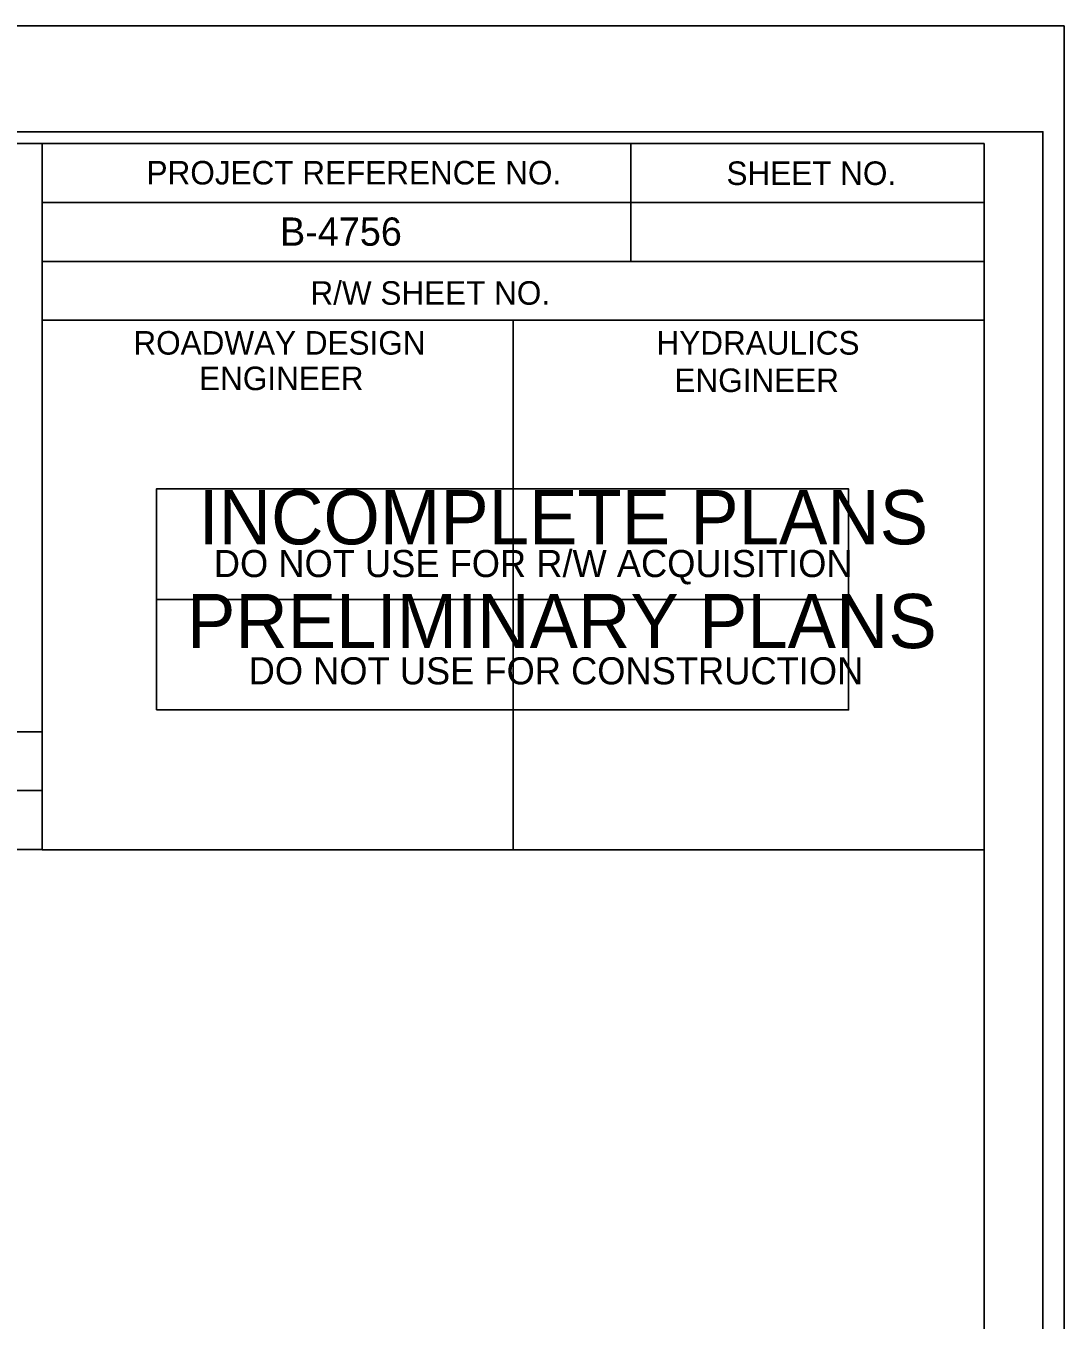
# Model space of a CAD drawing. Extents: x 2431000 to 2534000, y 645879 to 714000.
# Drawn here: x 2467565.7 to 2467786.2, y 672203.6 to 672478.6 of the extents above; entities that cross this region are included whole.
import ezdxf

# ---------------------------------------------------------------- set-up
doc = ezdxf.new("R2010")
doc.units = 0
for name, color, linetype in [('KHA_LOGO', 7, 'Continuous'), ('Prop Dimension', 7, 'Continuous'), ('Prop Dimension Text', 7, 'Continuous'), ('Prop Terminator CELL', 7, 'Continuous'), ('Sheet Clip Boundary CELL', 7, 'Continuous')]:
    doc.layers.add(name, color=color, linetype=linetype)

msp = doc.modelspace()

# ---------------------------------------------------------------- linework, layer by layer
at = {"layer": 'KHA_LOGO'}
for p, q in [((2467694.2, 672453.58), (2467694.2, 672428.58)), ((2467569.15, 672441.08), (2467769.2, 672441.08)), ((2467569.15, 672428.58), (2467769.2, 672428.58)), ((2467569.15, 672428.58), (2467569.15, 672416.08)), ((2467569.15, 672428.58), (2467769.2, 672428.58)), ((2467669.2, 672416.08), (2467669.2, 672303.63))]:
    msp.add_line(p, q, dxfattribs=at)
for points in [[(2467769.2, 672453.63), (2466269.2, 672453.63), (2466269.2, 671403.63), (2467769.2, 671403.63)], [(2467569.15, 672453.63), (2467769.2, 672453.63), (2467769.2, 672428.58), (2467569.15, 672428.58)], [(2467569.15, 672416.08), (2467669.2, 672416.08), (2467669.2, 672303.58), (2467569.15, 672303.58)], [(2467669.2, 672416.08), (2467769.2, 672416.08), (2467769.2, 672303.58), (2467669.2, 672303.58)]]:
    msp.add_lwpolyline(points, close=True, dxfattribs=at)
at = {"layer": 'Prop Dimension'}
msp.add_lwpolyline([(2466102.7, 671378.63), (2467786.2, 671378.63), (2467786.2, 672478.63), (2466102.7, 672478.63)], close=True, dxfattribs=at)
at = {"layer": 'Prop Dimension Text'}
for points in [[(2467593.43, 672356.76), (2467593.43, 672380.26), (2467740.43, 672380.26), (2467740.43, 672356.77)], [(2467593.43, 672333.27), (2467593.43, 672356.76), (2467740.43, 672356.77), (2467740.43, 672333.27)]]:
    msp.add_lwpolyline(points, close=True, dxfattribs=at)
at = {"layer": 'Prop Terminator CELL'}
msp.add_lwpolyline([(2466115.7, 671401.13), (2467781.7, 671401.13), (2467781.7, 672456.13), (2466115.7, 672456.13)], close=True, dxfattribs=at)
at = {"layer": 'Sheet Clip Boundary CELL'}
for points in [[(2467469.15, 672328.63), (2467569.15, 672328.63), (2467569.15, 672453.63), (2467469.15, 672453.63)], [(2467469.15, 672316.13), (2467569.15, 672316.13), (2467569.15, 672328.63), (2467469.15, 672328.63)], [(2467469.15, 672303.63), (2467569.15, 672303.63), (2467569.15, 672316.13), (2467469.15, 672316.13)]]:
    msp.add_lwpolyline(points, close=True, dxfattribs=at)

# ---------------------------------------------------------------- texts
at = {"layer": 'KHA_LOGO'}
for s, height, p in [('PROJECT REFERENCE NO.', 5.0001, (2467591.35, 672444.93)), ('SHEET NO.', 5, (2467714.5, 672444.83)), ('B-4756', 6, (2467619.69, 672431.92)), ('R/W SHEET NO.', 5.0001, (2467626.15, 672419.38)), ('ROADWAY DESIGN', 5.0001, (2467588.55, 672408.78)), ('HYDRAULICS', 5, (2467699.65, 672408.78)), ('ENGINEER', 5, (2467602.5, 672401.23)), ('ENGINEER', 5, (2467703.45, 672400.83))]:
    msp.add_text(s, height=height, dxfattribs=at).set_placement(p)
at = {"layer": 'Prop Dimension Text'}
for s, height, p in [('INCOMPLETE PLANS', 11.52, (2467602.38, 672368.47)), ('DO NOT USE FOR R/W ACQUISITION', 5.76, (2467605.63, 672361.51)), ('PRELIMINARY PLANS', 11.52, (2467599.93, 672346.41)), ('DO NOT USE FOR CONSTRUCTION', 5.76, (2467613.03, 672338.72))]:
    msp.add_text(s, height=height, dxfattribs=at).set_placement(p)

doc.saveas('drawing.dxf')
